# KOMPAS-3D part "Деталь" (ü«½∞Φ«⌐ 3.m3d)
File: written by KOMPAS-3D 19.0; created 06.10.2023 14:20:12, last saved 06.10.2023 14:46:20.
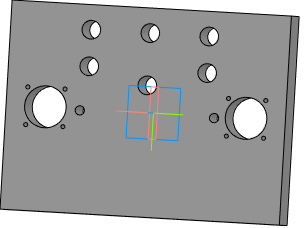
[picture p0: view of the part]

Document properties: Автор: admin; Организация: Hewlett-Packard Company; Полное имя файла: C:\Users\Petrenko-VE\Documents\Большой_3.m3d

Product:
- Part/product: Деталь
    Масса: 19.5407

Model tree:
1. Эскиз:1
2. Элемент выдавливания:1
     Расстояние 1 = 50
3. Эскиз:2  (with: Элемент выдавливания:1)
4. Элемент выдавливания:2
     Расстояние 2 = 50
5. Эскиз:3  (with: Элемент выдавливания:1, Элемент выдавливания:2)
6. Элемент выдавливания:3
     Расстояние 2 = 30
7. Эскиз:4  (with: Элемент выдавливания:1)
8. Элемент выдавливания:4
     Расстояние 2 = 50
9. Эскиз:5  (with: Элемент выдавливания:1, Элемент выдавливания:2)
10. Элемент выдавливания:5
     Расстояние 2 = 50
11. Эскиз:6  (with: Элемент выдавливания:1)
12. Элемент выдавливания:6
     Расстояние 2 = 50
13. Эскиз:7  (with: Элемент выдавливания:1)
14. Элемент выдавливания:7
     Расстояние 2 = 50
15. Эскиз:8  (with: Элемент выдавливания:1, Элемент выдавливания:6)
16. Элемент выдавливания:8
     Расстояние 2 = 30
